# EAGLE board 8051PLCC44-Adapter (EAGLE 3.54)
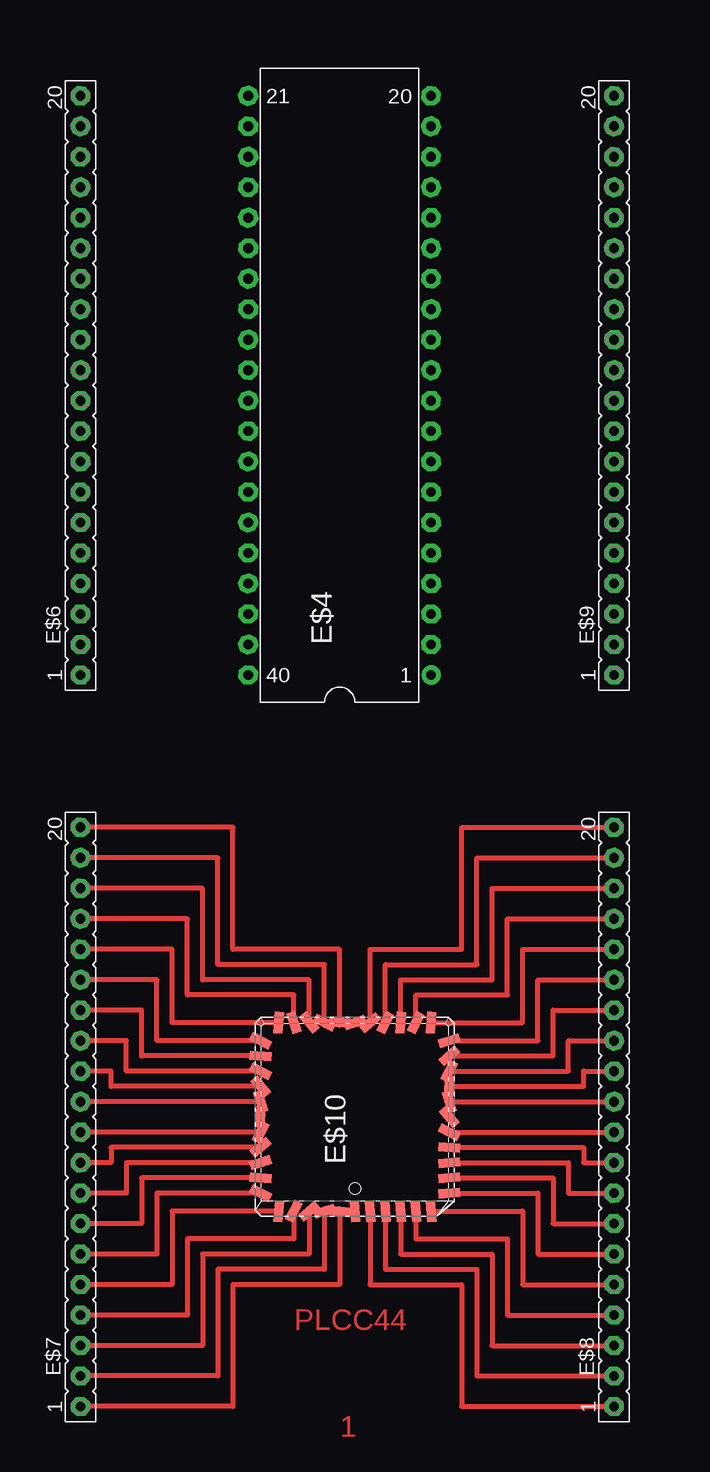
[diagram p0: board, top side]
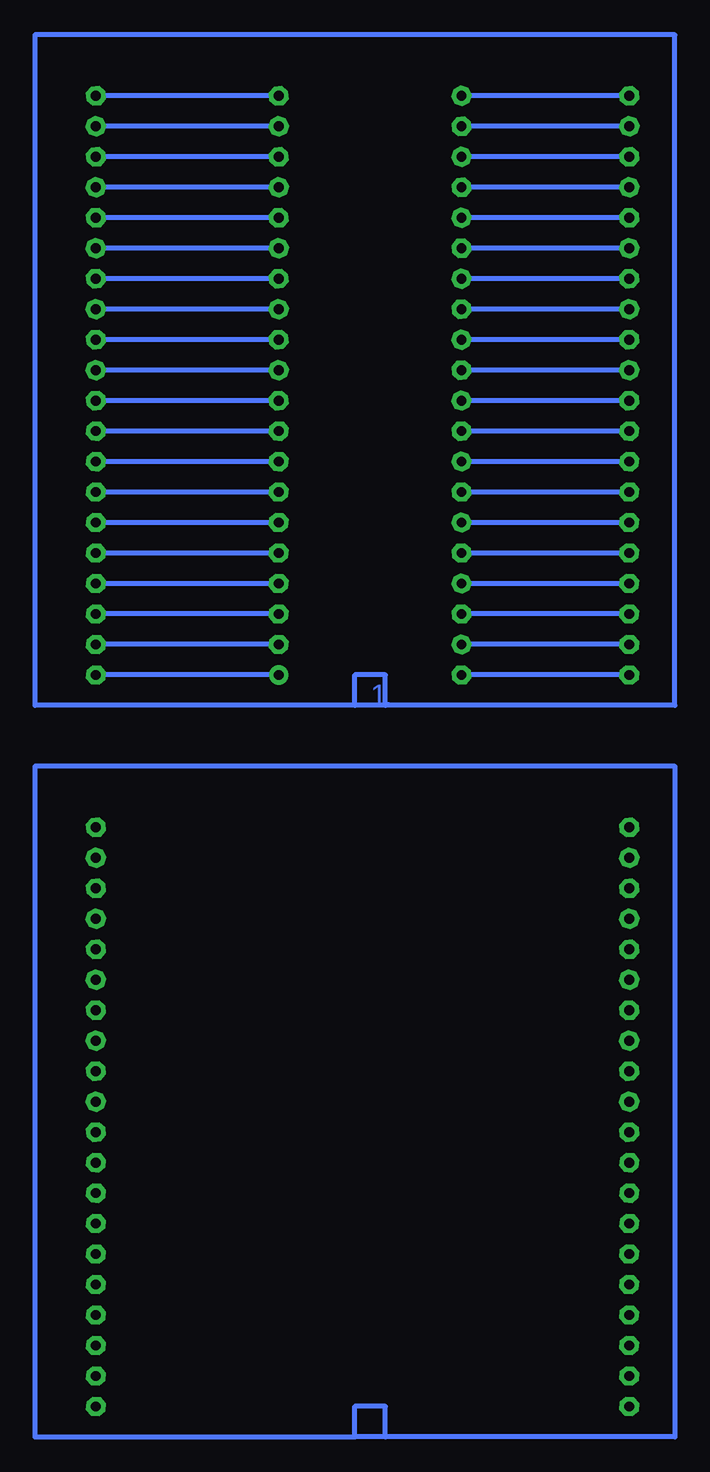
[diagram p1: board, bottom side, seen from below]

No outline drawn. Coordinates in mm, seen from the top.
Copper layers used: Top, Bottom

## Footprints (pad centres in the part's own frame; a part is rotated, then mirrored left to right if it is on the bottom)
L40 = drill 0.813 pad 1.6 round:  -24.13,-7.62 | drill 0.813 pad 1.6 octagon:  -21.59,-7.62;  -19.05,-7.62;  -16.51,-7.62;  -13.97,-7.62;  -11.43,-7.62;  -8.89,-7.62;  -6.35,-7.62;  -3.81,-7.62;  -1.27,-7.62;  1.27,-7.62;  3.81,-7.62;  6.35,-7.62;  8.89,-7.62;  11.43,-7.62;  13.97,-7.62;  16.51,-7.62;  19.05,-7.62;  21.59,-7.62;  24.13,-7.62;  24.13,7.62;  21.59,7.62;  19.05,7.62;  16.51,7.62;  13.97,7.62;  11.43,7.62;  8.89,7.62;  6.35,7.62;  3.81,7.62;  1.27,7.62;  -1.27,7.62;  -3.81,7.62;  -6.35,7.62;  -8.89,7.62;  -11.43,7.62;  -13.97,7.62;  -16.51,7.62;  -19.05,7.62;  -21.59,7.62;  -24.13,7.62
20 = drill 0.813 pad 1.6 octagon:  -24.13,0;  -21.59,0;  -19.05,0;  -16.51,0;  -13.97,0;  -11.43,0;  -8.89,0;  -6.35,0;  -3.81,0;  -1.27,0;  1.27,0;  3.81,0;  6.35,0;  8.89,0;  11.43,0;  13.97,0;  16.51,0;  19.05,0;  21.59,0;  24.13,0
CC-44 = smd 0.76 x 1.8 rotated 4.9:  -5.08,-7.86 | smd 0.76 x 1.8 rotated 5:  -3.81,-7.86 | smd 0.76 x 1.8 rotated 4.3:  -2.54,-7.86 | smd 0.76 x 1.8 rotated 26.8:  -1.27,-7.86 | smd 0.76 x 1.8 rotated 49.3:  0,-7.86 | smd 0.76 x 1.8 rotated 71.8:  1.27,-7.86 | smd 0.76 x 1.8 rotated 94.3:  2.54,-7.86 | smd 0.76 x 1.8 rotated 139.5:  -2.54,7.86 | smd 0.76 x 1.8 rotated 117:  -1.27,7.86 | smd 0.76 x 1.8 rotated 94.5:  0,7.86 | smd 0.76 x 1.8 rotated 72:  1.27,7.86 | smd 0.76 x 1.8 rotated 49.5:  2.54,7.86 | smd 0.76 x 1.8 rotated 27:  3.81,7.86 | smd 0.76 x 1.8 rotated 4.5:  5.08,7.86 | smd 1.8 x 0.76 rotated 4.7:  -7.86,-6.35;  -7.86,-5.08 | smd 1.8 x 0.76 rotated 4.5:  -7.86,-2.54 | smd 1.8 x 0.76 rotated 4.4:  -7.86,-1.27;  7.86,-3.81 | smd 1.8 x 0.76 rotated 4.3:  -7.86,0 | smd 1.8 x 0.76 rotated 94.6:  -7.86,1.27 | smd 1.8 x 0.76 rotated 72.1:  -7.86,2.54 | smd 1.8 x 0.76 rotated 49.6:  -7.86,3.81 | smd 1.8 x 0.76 rotated 184.3:  7.86,-6.35 | smd 1.8 x 0.76 rotated 26.9:  7.86,-2.54 | smd 1.8 x 0.76 rotated 49.4:  7.86,-1.27 | smd 1.8 x 0.76 rotated 71.9:  7.86,0 | smd 1.8 x 0.76 rotated 94.4:  7.86,1.27 | smd 1.8 x 0.76 rotated 116.9:  7.86,2.54 | smd 1.8 x 0.76 rotated 139.4:  7.86,3.81 | smd 0.76 x 1.8 rotated 116.8:  3.81,-7.86 | smd 0.76 x 1.8 rotated 139.3:  5.08,-7.86 | smd 0.76 x 1.8 rotated 162:  -3.81,7.86 | smd 0.76 x 1.8 rotated 184.5:  -5.08,7.86 | smd 0.76 x 1.8 rotated 206.9:  6.35,7.86 | smd 1.8 x 0.76 rotated 161.9:  7.86,5.08 | smd 1.8 x 0.76 rotated 184.4:  7.86,6.35 | smd 1.8 x 0.76 rotated 206.8:  7.86,-5.08 | smd 0.76 x 1.8 rotated 161.8:  6.35,-7.86 | smd 1.8 x 0.76 rotated 4.6:  -7.86,-3.81;  -7.86,6.35 | smd 1.8 x 0.76 rotated 27.1:  -7.86,5.08 | smd 0.76 x 1.8 rotated 207:  -6.35,7.86 | smd 0.76 x 1.8 rotated 4.8:  -6.35,-7.86

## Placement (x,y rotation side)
E$4  [L40]  35.56,35.56 90 top
E$6  [20]  13.97,35.56 90 top
E$7  [20]  13.97,-25.4 90 top
E$8  [20]  58.42,-25.4 90 top
E$9  [20]  58.42,35.56 90 top
E$10  [CC-44]  36.83,-25.4 90 top

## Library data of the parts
E$4 = DIL
E$6-E$9 = CON-LSTA
E$10 = SMD-IC

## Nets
S$1: E$4. E$6.
S$2: E$4. E$6.
S$3: E$4. E$6.
S$4: E$4. E$6.
S$5: E$4. E$6.
S$6: E$4. E$6.
S$7: E$4. E$6.
S$8: E$4. E$6.
S$9: E$4. E$6.
S$10: E$4. E$6.
S$11: E$4. E$6.
S$12: E$4. E$6.
S$13: E$4. E$6.
S$14: E$4. E$6.
S$15: E$4. E$6.
S$16: E$4. E$6.
S$17: E$4. E$6.
S$18: E$4. E$6.
S$19: E$4. E$6.
S$20: E$4. E$6.
S$21: E$4. E$9.
S$22: E$4. E$9.
S$23: E$4. E$9.
S$24: E$4. E$9.
S$25: E$4. E$9.
S$26: E$4. E$9.
S$27: E$4. E$9.
S$28: E$4. E$9.
S$29: E$4. E$9.
S$30: E$4. E$9.
S$31: E$4. E$9.
S$32: E$4. E$9.
S$33: E$8. E$10.
S$34: E$8. E$10.
S$35: E$8. E$10.
S$36: E$8. E$10.
S$37: E$8. E$10.
S$38: E$8. E$10.
S$39: E$8. E$10.
S$40: E$8. E$10.
S$41: E$8. E$10.
S$42: E$8. E$10.
S$43: E$8. E$10.
S$44: E$8. E$10.
S$45: E$8. E$10.
S$46: E$8. E$10.
S$47: E$8. E$10.
S$48: E$8. E$10.
S$49: E$8. E$10.
S$50: E$8. E$10.
S$51: E$8. E$10.
S$52: E$8. E$10.
S$53: E$7. E$10.
S$54: E$7. E$10.
S$55: E$7. E$10.
S$56: E$7. E$10.
S$57: E$7. E$10.
S$58: E$7. E$10.
S$59: E$7. E$10.
S$60: E$7. E$10.
S$61: E$7. E$10.
S$62: E$7. E$10.
S$63: E$7. E$10.
S$64: E$7. E$10.
S$67: E$4. E$9.
S$68: E$7. E$10.
S$70: E$4. E$9.
S$71: E$4. E$9.
S$72: E$4. E$9.
S$73: E$4. E$9.
S$74: E$4. E$9.
S$75: E$4. E$9.
S$76: E$4. E$9.
S$77: E$7. E$10.
S$78: E$7. E$10.
S$79: E$7. E$10.
S$80: E$7. E$10.
S$81: E$7. E$10.
S$82: E$7. E$10.
S$83: E$7. E$10.

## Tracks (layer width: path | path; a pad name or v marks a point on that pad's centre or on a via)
S$1
  Bottom 0.406: E$6. 27.94,59.69
S$2
  Bottom 0.406: 13.97,57.15 27.94,57.15
S$3
  Bottom 0.406: 13.97,54.61 27.94,54.61
S$4
  Bottom 0.406: 13.97,52.07 27.94,52.07
S$5
  Bottom 0.406: 13.97,49.53 27.94,49.53
S$6
  Bottom 0.406: 13.97,46.99 27.94,46.99
S$7
  Bottom 0.406: 13.97,44.45 27.94,44.45
S$8
  Bottom 0.406: 13.97,41.91 27.94,41.91
S$9
  Bottom 0.406: 13.97,39.37 27.94,39.37
S$10
  Bottom 0.406: 13.97,36.83 27.94,36.83
S$11
  Bottom 0.406: 13.97,34.29 27.94,34.29
S$12
  Bottom 0.406: 13.97,31.75 27.94,31.75
S$13
  Bottom 0.406: 13.97,29.21 27.94,29.21
S$14
  Bottom 0.406: 13.97,26.67 27.94,26.67
S$15
  Bottom 0.406: 13.97,24.13 27.94,24.13
S$16
  Bottom 0.406: 13.97,21.59 27.94,21.59
S$17
  Bottom 0.406: 13.97,19.05 27.94,19.05
S$18
  Bottom 0.406: 13.97,16.51 27.94,16.51
S$19
  Bottom 0.406: 13.97,13.97 27.94,13.97
S$20
  Bottom 0.406: 13.97,11.43 E$4.
S$21
  Bottom 0.406: 43.18,11.43 58.42,11.43
S$22
  Bottom 0.406: 43.18,13.97 58.42,13.97
S$23
  Bottom 0.406: 43.18,16.51 58.42,16.51
S$24
  Bottom 0.406: 43.18,19.05 58.42,19.05
S$25
  Bottom 0.406: 43.18,21.59 58.42,21.59
S$26
  Bottom 0.406: 43.18,24.13 58.42,24.13
S$27
  Bottom 0.406: 43.18,26.67 58.42,26.67
S$28
  Bottom 0.406: 43.18,29.21 58.42,29.21
S$29
  Bottom 0.406: 43.18,31.75 58.42,31.75
S$30
  Bottom 0.406: 43.18,34.29 58.42,34.29
S$31
  Bottom 0.406: 43.18,36.83 58.42,36.83
S$32
  Bottom 0.406: 43.18,39.37 58.42,39.37
S$33
  Top 0.406: 38.1,-33.02 38.1,-33.26 38.1,-39.37 45.72,-39.37 45.72,-49.53 58.42,-49.53
S$34
  Top 0.406: 39.37,-33.02 39.37,-33.26 39.37,-38.1 46.99,-38.1 46.99,-46.99 58.42,-46.99
S$35
  Top 0.406: 40.64,-33.02 40.64,-33.26 40.64,-36.83 48.26,-36.83 48.26,-44.45 58.42,-44.45
S$36
  Top 0.406: 41.91,-33.02 41.91,-33.26 41.91,-35.56 49.53,-35.56 49.53,-41.91 58.42,-41.91
S$37
  Top 0.406: 43.18,-33.02 43.18,-33.26 50.8,-33.26 50.8,-39.37 58.42,-39.37
S$38
  Top 0.406: E$10. 52.07,-31.75 52.07,-36.83 58.42,-36.83
S$39
  Top 0.406: 44.45,-30.48 44.69,-30.48 53.34,-30.48 53.34,-34.29 58.42,-34.29
S$40
  Top 0.406: 44.45,-29.21 44.69,-29.21 54.61,-29.21 54.61,-31.75 58.42,-31.75
S$41
  Top 0.406: 44.45,-27.94 44.69,-27.94 55.88,-27.94 55.88,-29.21 58.42,-29.21
S$42
  Top 0.406: 44.69,-26.67 58.42,-26.67
S$43
  Top 0.406: 44.45,-24.13 44.69,-24.13 58.42,-24.13
S$44
  Top 0.406: 44.45,-22.86 44.69,-22.86 55.88,-22.86 55.88,-21.59 58.42,-21.59
S$45
  Top 0.406: 44.45,-21.59 44.69,-21.59 54.61,-21.59 54.61,-19.05 58.42,-19.05
S$46
  Top 0.406: 44.45,-20.32 44.69,-20.32 53.34,-20.32 53.34,-16.51 58.42,-16.51
S$47
  Top 0.406: 44.69,-19.05 52.07,-19.05 52.07,-13.97 58.42,-13.97
S$48
  Top 0.406: 43.18,-17.54 50.8,-17.54 50.8,-11.43 58.42,-11.43
S$49
  Top 0.406: 41.91,-17.54 41.91,-15.24 49.53,-15.24 49.53,-8.89 58.42,-8.89
S$50
  Top 0.406: 40.64,-17.78 40.64,-17.54 40.64,-13.97 48.26,-13.97 48.26,-6.35 58.42,-6.35
S$51
  Top 0.406: 39.37,-17.78 39.37,-17.54 39.37,-12.7 46.99,-12.7 46.99,-3.81 58.42,-3.81
S$52
  Top 0.406: 38.1,-17.78 38.1,-17.54 38.1,-11.43 45.72,-11.43 45.72,-1.27 E$8.
S$53
  Top 0.406: 35.56,-17.78 35.56,-17.54 35.56,-11.43 26.67,-11.43 26.67,-1.27 E$7.
S$54
  Top 0.406: 34.29,-17.78 34.29,-17.54 34.29,-12.7 25.4,-12.7 25.4,-3.81 13.97,-3.81
S$55
  Top 0.406: 33.02,-17.78 33.02,-17.54 33.02,-13.97 24.13,-13.97 24.13,-6.35 13.97,-6.35
S$56
  Top 0.406: 31.75,-17.78 31.75,-17.54 31.75,-15.24 22.86,-15.24 22.86,-8.89 13.97,-8.89
S$57
  Top 0.406: 30.48,-17.78 30.48,-17.54 21.59,-17.54 21.59,-11.43 13.97,-11.43
S$58
  Top 0.406: 28.97,-19.05 20.32,-19.05 20.32,-13.97 13.97,-13.97
S$59
  Top 0.406: 29.21,-20.32 28.97,-20.32 19.05,-20.32 19.05,-16.51 13.97,-16.51
S$60
  Top 0.406: 29.21,-21.59 28.97,-21.59 17.78,-21.59 17.78,-19.05 13.97,-19.05
S$61
  Top 0.406: 29.21,-22.86 28.97,-22.86 16.51,-22.86 16.51,-21.59 13.97,-21.59
S$62
  Top 0.406: 29.21,-24.13 28.97,-24.13 13.97,-24.13
S$63
  Top 0.406: 29.21,-26.67 28.97,-26.67 13.97,-26.67
S$64
  Top 0.406: 29.21,-27.94 28.97,-27.94 16.51,-27.94 16.51,-29.21 13.97,-29.21
S$65
  Bottom 0.406: 36.83,8.89 63.5,8.89 63.5,64.77 10.16,64.77 10.16,8.89 34.29,8.89 | 36.83,8.89 36.83,11.43 34.29,11.43 34.29,8.89 | 34.29,8.89 36.83,8.89
S$66
  Bottom 0.406: 34.29,-52.07 10.16,-52.07 10.16,3.81 63.5,3.81 63.5,-52.07 36.83,-52.07 | 34.29,-52.07 36.83,-52.07 | 34.29,-52.07 34.29,-49.53 36.83,-49.53 36.83,-52.07
S$67
  Bottom 0.406: 43.18,41.91 58.42,41.91
S$68
  Top 0.406: 29.21,-29.21 28.97,-29.21 17.78,-29.21 17.78,-31.75 13.97,-31.75
S$69
  Bottom 0.406: 33.96,8.93 34.26,8.93
S$70
  Bottom 0.406: 43.18,44.45 58.42,44.45
S$71
  Bottom 0.406: 43.18,46.99 58.42,46.99
S$72
  Bottom 0.406: 43.18,49.53 58.42,49.53
S$73
  Bottom 0.406: 43.18,52.07 58.42,52.07
S$74
  Bottom 0.406: 43.18,54.61 58.42,54.61
S$75
  Bottom 0.406: 43.18,57.15 58.42,57.15
S$76
  Bottom 0.406: 43.18,59.69 E$9.
S$77
  Top 0.406: 29.21,-30.48 28.97,-30.48 19.05,-30.48 19.05,-34.29 13.97,-34.29
S$78
  Top 0.406: 29.21,-31.75 28.97,-31.75 20.32,-31.75 20.32,-36.83 13.97,-36.83
S$79
  Top 0.406: 30.48,-33.02 30.48,-33.26 21.59,-33.26 21.59,-39.37 13.97,-39.37
S$80
  Top 0.406: 31.75,-33.02 31.75,-33.26 31.75,-35.56 22.86,-35.56 22.86,-41.91 13.97,-41.91
S$81
  Top 0.406: 33.02,-33.02 33.02,-33.26 33.02,-36.83 24.13,-36.83 24.13,-44.45 13.97,-44.45
S$82
  Top 0.406: 34.29,-33.02 34.29,-33.26 34.29,-38.1 25.4,-38.1 25.4,-46.99 13.97,-46.99
S$83
  Top 0.406: 35.56,-33.02 35.56,-33.26 35.56,-39.37 26.67,-39.37 26.67,-49.53 13.97,-49.53

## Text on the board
Top: PLCC44 | 1
Bottom: 1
